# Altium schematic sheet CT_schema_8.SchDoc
size 278 x 170 mm
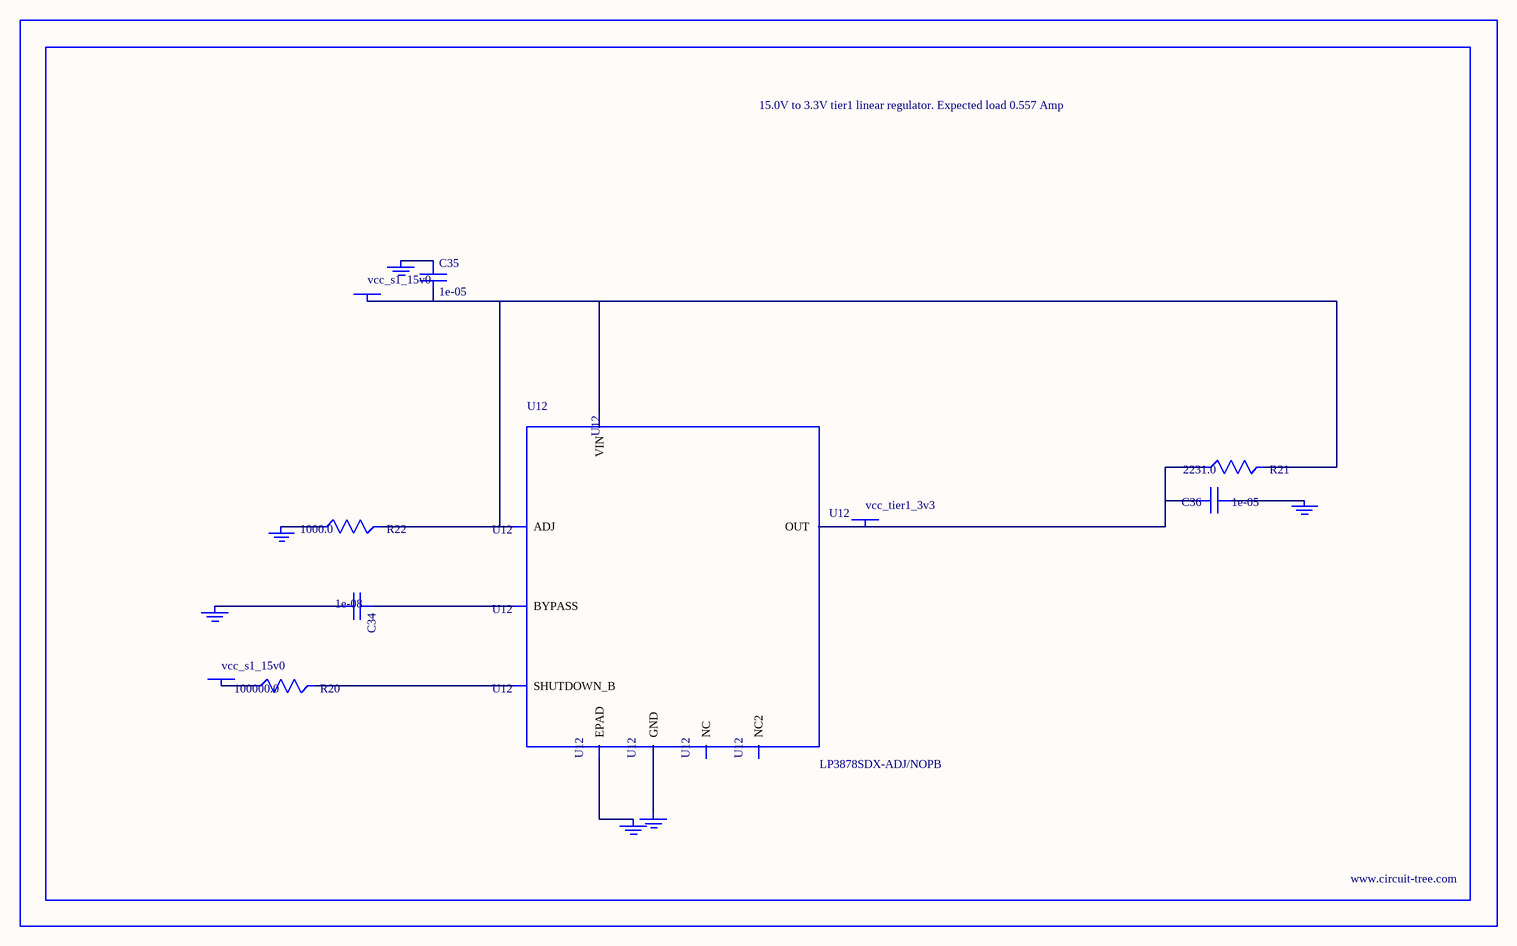
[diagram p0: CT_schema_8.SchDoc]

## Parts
BORDER7  (no value)
C34  1e-08  [C0402]
C35  1e-05  [C1210]
C36  1e-05  [C1210]
GND_INSTANCE_7_0  (no value)
GND_INSTANCE_7_1  (no value)
GND_INSTANCE_7_2  (no value)
GND_INSTANCE_7_3  (no value)
GND_INSTANCE_7_4  (no value)
GND_INSTANCE_7_5  (no value)
POWER_INSTANCE_7_0  vcc_s1_15v0
POWER_INSTANCE_7_1  vcc_s1_15v0
POWER_INSTANCE_7_2  vcc_tier1_3v3
R20  100000.0  [R0603]
R21  2231.0  [R0603]
R22  1000.0  [R0603]
U12  LP3878SDX-ADJ/NOPB  [WSON-8]

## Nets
NetC34_1: C34.1 U12.1(BYPASS)
NetC34_2: C34.2 GND_INSTANCE_7_0.0(GND)
NetC35_1: C35.1 GND_INSTANCE_7_1.0(GND)
NetC35_2: C35.2 POWER_INSTANCE_7_0.0(PWR) R21.2 R22.2 U12.4(VIN) U12.6(ADJ)
NetC36_1: C36.1 GND_INSTANCE_7_2.0(GND)
NetC36_2: C36.2 POWER_INSTANCE_7_2.0(PWR) R21.1 U12.5(OUT)
NetGND_INSTANCE_7_3_0: GND_INSTANCE_7_3.0(GND) R22.1
NetGND_INSTANCE_7_4_0: GND_INSTANCE_7_4.0(GND) U12.PAD(EPAD)
NetGND_INSTANCE_7_5_0: GND_INSTANCE_7_5.0(GND) U12.3(GND)
NetPOWER_INSTANCE_7_1_0: POWER_INSTANCE_7_1.0(PWR) R20.1
NetR20_2: R20.2 U12.8(SHUTDOWN_B)

Not connected (* = marked no-connect by the designer): U12 2(NC) 7(NC2)

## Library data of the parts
BORDER7 = BORDER_PAGE7
C34 = C0402C103K3RAC
C35 = C1210C106K5PACTU
C36 = GRM32DR61E106MA12L
GND_INSTANCE_7_0-GND_INSTANCE_7_5 = GND
POWER_INSTANCE_7_0-POWER_INSTANCE_7_2 = PWR
R20 = RC0603JR-07100KL
R21 = R21
R22 = RC0603JR-071KL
